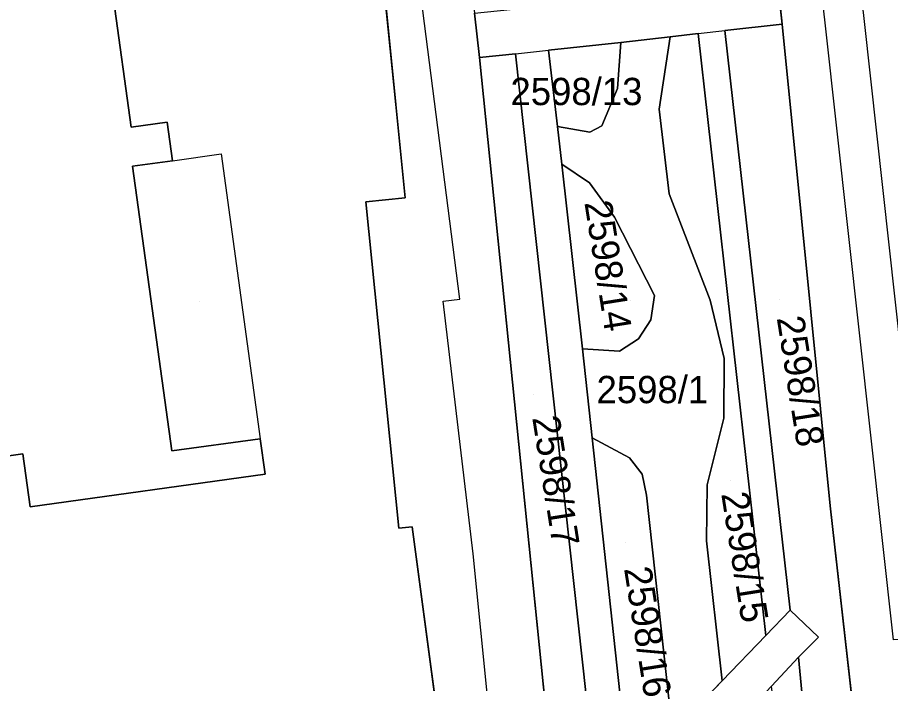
# Model space of a CAD drawing. Extents: x -263423 to -261326, y -1240067 to -1237864.
# Drawn here: x -263224.1 to -263160.1, y -1239953.5 to -1239904.7 of the extents above; entities that cross this region are included whole.
import ezdxf

# ---------------------------------------------------------------- set-up
doc = ezdxf.new("R2010")
doc.units = 0
for name, color, linetype in [('body_kn', 7, 'Continuous'), ('kladpar_druhypozemkov', 7, 'Continuous'), ('kladpar_hranice', 7, 'Continuous'), ('kladpar_parcelnecisla', 7, 'Continuous'), ('kladpar_plochy', 7, 'Continuous'), ('tarchy_linie', 7, 'Continuous'), ('zappar_hrandruhpozemk', 7, 'Continuous')]:
    doc.layers.add(name, color=color, linetype=linetype)

msp = doc.modelspace()

# ---------------------------------------------------------------- linework, layer by layer
at = {"layer": 'body_kn'}
for p, q in [((-263168.05, -1239905.15), (-263168.05, -1239905.15)), ((-263164.87, -1239905.28), (-263164.87, -1239905.28)), ((-263162.04, -1239904.96), (-263162.04, -1239904.96)), ((-263174.2, -1239905.83), (-263174.2, -1239905.83)), ((-263174.2, -1239905.83), (-263174.2, -1239905.83)), ((-263172.25, -1239905.62), (-263172.25, -1239905.62)), ((-263172.25, -1239905.62), (-263172.25, -1239905.62)), ((-263179.86, -1239906.49), (-263179.86, -1239906.49)), ((-263179.86, -1239906.49), (-263179.86, -1239906.49)), ((-263176.25, -1239906.08), (-263176.25, -1239906.08)), ((-263176.25, -1239906.08), (-263176.25, -1239906.08)), ((-263185.17, -1239907.05), (-263185.17, -1239907.05)), ((-263185.17, -1239907.05), (-263185.17, -1239907.05)), ((-263190.22, -1239907.6), (-263190.22, -1239907.6)), ((-263190.22, -1239907.6), (-263190.22, -1239907.6)), ((-263187.59, -1239907.31), (-263187.59, -1239907.31)), ((-263187.59, -1239907.31), (-263187.59, -1239907.31)), ((-263180.1, -1239909.85), (-263180.1, -1239909.85)), ((-263196.35, -1239911.03), (-263196.35, -1239911.03)), ((-263177.05, -1239911.38), (-263177.05, -1239911.38)), ((-263213.1, -1239912.33), (-263213.1, -1239912.33)), ((-263215.73, -1239912.69), (-263215.73, -1239912.69)), ((-263184.51, -1239912.65), (-263184.51, -1239912.65)), ((-263181.26, -1239912.6), (-263181.26, -1239912.6)), ((-263182.13, -1239913.06), (-263182.13, -1239913.06)), ((-263209.14, -1239914.66), (-263209.14, -1239914.66)), ((-263212.71, -1239915.15), (-263212.71, -1239915.15)), ((-263212.71, -1239915.15), (-263212.71, -1239915.15)), ((-263184.18, -1239915.4), (-263184.18, -1239915.4)), ((-263184.18, -1239915.4), (-263184.18, -1239915.4)), ((-263215.62, -1239915.55), (-263215.62, -1239915.55)), ((-263182.17, -1239916.78), (-263182.17, -1239916.78)), ((-263195.65, -1239917.88), (-263195.65, -1239917.88)), ((-263176.32, -1239917.58), (-263176.32, -1239917.58)), ((-263198.53, -1239918.17), (-263198.53, -1239918.17)), ((-263180.32, -1239919.28), (-263180.32, -1239919.28)), ((-263177.39, -1239925.04), (-263177.39, -1239925.04)), ((-263192.87, -1239925.44), (-263192.87, -1239925.44)), ((-263191.66, -1239925.31), (-263191.66, -1239925.31)), ((-263173.31, -1239925.38), (-263173.31, -1239925.38)), ((-263177.66, -1239926.81), (-263177.66, -1239926.81)), ((-263178.56, -1239928.2), (-263178.56, -1239928.2)), ((-263182.68, -1239928.94), (-263182.68, -1239928.94)), ((-263179.95, -1239929.11), (-263179.95, -1239929.11)), ((-263172.29, -1239929.64), (-263172.29, -1239929.64)), ((-263172.32, -1239934.02), (-263172.32, -1239934.02)), ((-263206.27, -1239935.53), (-263206.27, -1239935.53)), ((-263181.97, -1239935.45), (-263181.97, -1239935.45)), ((-263181.97, -1239935.45), (-263181.97, -1239935.45)), ((-263212.75, -1239936.42), (-263212.75, -1239936.42)), ((-263223.67, -1239936.64), (-263223.67, -1239936.64)), ((-263179.23, -1239936.92), (-263179.23, -1239936.92)), ((-263205.91, -1239938.12), (-263205.91, -1239938.12)), ((-263178.31, -1239938.12), (-263178.31, -1239938.12)), ((-263173.54, -1239938.91), (-263173.54, -1239938.91)), ((-263177.98, -1239939.66), (-263177.98, -1239939.66)), ((-263164.52, -1239940.44), (-263164.52, -1239940.44)), ((-263223.13, -1239940.51), (-263223.13, -1239940.51)), ((-263196.12, -1239942.09), (-263196.12, -1239942.09)), ((-263195.14, -1239941.99), (-263195.14, -1239941.99)), ((-263173.59, -1239943), (-263173.59, -1239943)), ((-263190.68, -1239943.95), (-263190.68, -1239943.95)), ((-263167.47, -1239948.09), (-263167.47, -1239948.09)), ((-263169.24, -1239949.95), (-263169.24, -1239949.95)), ((-263169.24, -1239949.95), (-263169.24, -1239949.95)), ((-263165.39, -1239950.06), (-263165.39, -1239950.06)), ((-263166.86, -1239951.52), (-263166.86, -1239951.52)), ((-263172.45, -1239953.27), (-263172.45, -1239953.27))]:
    msp.add_line(p, q, dxfattribs=at)
at = {"layer": 'kladpar_druhypozemkov'}
for p, q in [((-263182.81, -1239908.62), (-263182.81, -1239908.62)), ((-263210.71, -1239925.47), (-263210.71, -1239925.47)), ((-263179.12, -1239925.4), (-263179.12, -1239925.4)), ((-263168.22, -1239925.29), (-263168.22, -1239925.29)), ((-263177.05, -1239931.08), (-263177.05, -1239931.08)), ((-263186.24, -1239932.27), (-263186.24, -1239932.27)), ((-263171.86, -1239938.61), (-263171.86, -1239938.61)), ((-263179.51, -1239943.11), (-263179.51, -1239943.11))]:
    msp.add_line(p, q, dxfattribs=at)
at = {"layer": 'kladpar_hranice'}
for points in [[(-263193.38, -1239955.18), (-263195.14, -1239941.99), (-263196.12, -1239942.09), (-263198.53, -1239918.17), (-263195.65, -1239917.88), (-263196.35, -1239911.03), (-263197.17, -1239902.86), (-263197.96, -1239896), (-263200.87, -1239896.38), (-263203.98, -1239872.45), (-263202.98, -1239872.32), (-263204.71, -1239859.15), (-263204.77, -1239856.81), (-263205.86, -1239847.27), (-263207.6, -1239832.39), (-263207.79, -1239830.68)], [(-263161.9, -1239963.77), (-263164.52, -1239940.44), (-263168.05, -1239905.15), (-263168.4, -1239901.9), (-263174.54, -1239845.62), (-263175.4, -1239842.65), (-263176.71, -1239841.42), (-263179.47, -1239841.16), (-263194.58, -1239842.51), (-263196.99, -1239843.82), (-263197.78, -1239846.18), (-263196.99, -1239852.35), (-263190.58, -1239904.35), (-263190.22, -1239907.6), (-263184.32, -1239965.74)], [(-263178.81, -1239846.85), (-263172.6, -1239902.36), (-263168.4, -1239901.9), (-263168.05, -1239905.15), (-263172.25, -1239905.62), (-263167.47, -1239948.09), (-263165.39, -1239950.06), (-263166.86, -1239951.52), (-263165.62, -1239964.33), (-263167.57, -1239964.63), (-263168.82, -1239953.66), (-263172.04, -1239957.08), (-263175.64, -1239960.83), (-263178.87, -1239964.17), (-263178.63, -1239966.32), (-263181.06, -1239966.48), (-263184.15, -1239967.16), (-263184.32, -1239965.74), (-263181.47, -1239962.77), (-263187.59, -1239907.31), (-263190.22, -1239907.6), (-263190.58, -1239904.35), (-263187.96, -1239904.06)], [(-263244.26, -1239865.92), (-263215.75, -1239862.51), (-263215.99, -1239860.48), (-263204.71, -1239859.15), (-263202.98, -1239872.32), (-263203.98, -1239872.45), (-263200.87, -1239896.38), (-263197.96, -1239896), (-263197.17, -1239902.86), (-263196.35, -1239911.03), (-263195.65, -1239917.88), (-263198.53, -1239918.17), (-263196.12, -1239942.09), (-263195.14, -1239941.99), (-263193.38, -1239955.18)], [(-263239.81, -1239883.6), (-263231.06, -1239882.45), (-263231.59, -1239878.45), (-263214.34, -1239876.16), (-263213.98, -1239878.84), (-263220.46, -1239879.71), (-263217.65, -1239900.62), (-263214.77, -1239900.23), (-263214.4, -1239902.93), (-263217.02, -1239903.29), (-263215.73, -1239912.69), (-263213.1, -1239912.33), (-263212.71, -1239915.15), (-263215.62, -1239915.55), (-263212.75, -1239936.42), (-263206.27, -1239935.53), (-263205.91, -1239938.12), (-263223.13, -1239940.51), (-263223.67, -1239936.64), (-263229.66, -1239937.48)], [(-263229.66, -1239937.48), (-263223.67, -1239936.64), (-263223.13, -1239940.51), (-263205.91, -1239938.12), (-263206.27, -1239935.53), (-263212.75, -1239936.42), (-263215.62, -1239915.55), (-263212.71, -1239915.15), (-263213.1, -1239912.33), (-263215.73, -1239912.69), (-263217.02, -1239903.29), (-263214.4, -1239902.93), (-263214.77, -1239900.23), (-263217.65, -1239900.62), (-263220.46, -1239879.71), (-263213.98, -1239878.84), (-263214.34, -1239876.16), (-263231.59, -1239878.45), (-263231.06, -1239882.45)], [(-263172.25, -1239905.62), (-263168.05, -1239905.15), (-263164.52, -1239940.44), (-263161.9, -1239963.77), (-263165.62, -1239964.33), (-263166.86, -1239951.52), (-263165.39, -1239950.06), (-263167.47, -1239948.09), (-263172.25, -1239905.62)], [(-263185.17, -1239907.05), (-263184.51, -1239912.65), (-263184.18, -1239915.4), (-263182.68, -1239928.94), (-263181.97, -1239935.45), (-263179.26, -1239960.44), (-263176.07, -1239957.04), (-263172.45, -1239953.27), (-263169.24, -1239949.95), (-263174.2, -1239905.83), (-263176.25, -1239906.08), (-263179.86, -1239906.49), (-263185.17, -1239907.05)], [(-263176.25, -1239906.08), (-263174.2, -1239905.83), (-263169.24, -1239949.95), (-263172.45, -1239953.27), (-263173.59, -1239943), (-263173.54, -1239938.91), (-263172.32, -1239934.02), (-263172.29, -1239929.64), (-263173.31, -1239925.38), (-263176.32, -1239917.58), (-263177.05, -1239911.38), (-263176.25, -1239906.08)], [(-263185.17, -1239907.05), (-263179.86, -1239906.49), (-263180.1, -1239909.85), (-263181.26, -1239912.6), (-263182.13, -1239913.06), (-263184.51, -1239912.65), (-263185.17, -1239907.05)], [(-263179.86, -1239906.49), (-263176.25, -1239906.08), (-263177.05, -1239911.38), (-263176.32, -1239917.58), (-263173.31, -1239925.38), (-263172.29, -1239929.64), (-263172.32, -1239934.02), (-263173.54, -1239938.91), (-263173.59, -1239943), (-263172.45, -1239953.27), (-263176.07, -1239957.04), (-263177.98, -1239939.66), (-263178.31, -1239938.12), (-263179.23, -1239936.92), (-263181.97, -1239935.45), (-263182.68, -1239928.94), (-263179.95, -1239929.11), (-263178.56, -1239928.2), (-263177.66, -1239926.81), (-263177.39, -1239925.04), (-263180.32, -1239919.28), (-263182.17, -1239916.78), (-263184.18, -1239915.4), (-263184.51, -1239912.65), (-263182.13, -1239913.06), (-263181.26, -1239912.6), (-263180.1, -1239909.85), (-263179.86, -1239906.49)], [(-263190.22, -1239907.6), (-263187.59, -1239907.31), (-263181.47, -1239962.77), (-263184.32, -1239965.74), (-263190.22, -1239907.6)], [(-263184.18, -1239915.4), (-263182.17, -1239916.78), (-263180.32, -1239919.28), (-263177.39, -1239925.04), (-263177.66, -1239926.81), (-263178.56, -1239928.2), (-263179.95, -1239929.11), (-263182.68, -1239928.94), (-263184.18, -1239915.4)], [(-263181.97, -1239935.45), (-263179.23, -1239936.92), (-263178.31, -1239938.12), (-263177.98, -1239939.66), (-263176.07, -1239957.04), (-263179.26, -1239960.44), (-263181.97, -1239935.45)]]:
    msp.add_lwpolyline(points, dxfattribs=at)
at = {"layer": 'kladpar_plochy'}
for p, q in [((-263168.4, -1239901.9), (-263168.05, -1239905.15)), ((-263168.05, -1239905.15), (-263168.4, -1239901.9)), ((-263215.73, -1239912.69), (-263217.02, -1239903.29)), ((-263197.17, -1239902.86), (-263196.35, -1239911.03)), ((-263196.35, -1239911.03), (-263197.17, -1239902.86)), ((-263190.22, -1239907.6), (-263190.58, -1239904.35)), ((-263190.58, -1239904.35), (-263190.22, -1239907.6)), ((-263168.05, -1239905.15), (-263172.25, -1239905.62)), ((-263164.52, -1239940.44), (-263168.05, -1239905.15)), ((-263174.2, -1239905.83), (-263176.25, -1239906.08)), ((-263169.24, -1239949.95), (-263174.2, -1239905.83)), ((-263172.25, -1239905.62), (-263167.47, -1239948.09)), ((-263179.86, -1239906.49), (-263185.17, -1239907.05)), ((-263176.25, -1239906.08), (-263179.86, -1239906.49)), ((-263185.17, -1239907.05), (-263184.51, -1239912.65)), ((-263187.59, -1239907.31), (-263190.22, -1239907.6)), ((-263190.22, -1239907.6), (-263184.32, -1239965.74)), ((-263181.47, -1239962.77), (-263187.59, -1239907.31)), ((-263196.35, -1239911.03), (-263195.65, -1239917.88)), ((-263195.65, -1239917.88), (-263196.35, -1239911.03)), ((-263213.1, -1239912.33), (-263215.73, -1239912.69)), ((-263212.71, -1239915.15), (-263213.1, -1239912.33)), ((-263184.51, -1239912.65), (-263184.18, -1239915.4)), ((-263215.62, -1239915.55), (-263212.71, -1239915.15)), ((-263184.18, -1239915.4), (-263182.68, -1239928.94)), ((-263212.75, -1239936.42), (-263215.62, -1239915.55)), ((-263195.65, -1239917.88), (-263198.53, -1239918.17)), ((-263198.53, -1239918.17), (-263195.65, -1239917.88)), ((-263198.53, -1239918.17), (-263196.12, -1239942.09)), ((-263196.12, -1239942.09), (-263198.53, -1239918.17)), ((-263182.68, -1239928.94), (-263181.97, -1239935.45)), ((-263206.27, -1239935.53), (-263212.75, -1239936.42)), ((-263205.91, -1239938.12), (-263206.27, -1239935.53)), ((-263181.97, -1239935.45), (-263179.26, -1239960.44)), ((-263229.66, -1239937.48), (-263223.67, -1239936.64)), ((-263223.67, -1239936.64), (-263223.13, -1239940.51)), ((-263223.13, -1239940.51), (-263205.91, -1239938.12)), ((-263161.9, -1239963.77), (-263164.52, -1239940.44)), ((-263196.12, -1239942.09), (-263195.14, -1239941.99)), ((-263195.14, -1239941.99), (-263196.12, -1239942.09)), ((-263195.14, -1239941.99), (-263193.38, -1239955.18)), ((-263193.38, -1239955.18), (-263195.14, -1239941.99)), ((-263167.47, -1239948.09), (-263165.39, -1239950.06)), ((-263172.45, -1239953.27), (-263169.24, -1239949.95)), ((-263165.39, -1239950.06), (-263166.86, -1239951.52)), ((-263166.86, -1239951.52), (-263165.62, -1239964.33)), ((-263176.07, -1239957.04), (-263172.45, -1239953.27))]:
    msp.add_line(p, q, dxfattribs=at)
msp.add_lwpolyline([(-263231.59, -1239878.45), (-263214.34, -1239876.16), (-263213.98, -1239878.84), (-263220.46, -1239879.71), (-263217.65, -1239900.62), (-263214.77, -1239900.23), (-263214.4, -1239902.93), (-263217.02, -1239903.29), (-263215.73, -1239912.69), (-263213.1, -1239912.33), (-263212.71, -1239915.15), (-263215.62, -1239915.55), (-263212.75, -1239936.42), (-263206.27, -1239935.53), (-263205.91, -1239938.12), (-263223.13, -1239940.51), (-263223.67, -1239936.64), (-263229.66, -1239937.48)], dxfattribs=at)
for points in [[(-263172.25, -1239905.62), (-263168.05, -1239905.15), (-263164.52, -1239940.44), (-263161.9, -1239963.77), (-263165.62, -1239964.33), (-263166.86, -1239951.52), (-263165.39, -1239950.06), (-263167.47, -1239948.09)], [(-263176.25, -1239906.08), (-263174.2, -1239905.83), (-263169.24, -1239949.95), (-263172.45, -1239953.27), (-263173.59, -1239943), (-263173.54, -1239938.91), (-263172.32, -1239934.02), (-263172.29, -1239929.64), (-263173.31, -1239925.38), (-263176.32, -1239917.58), (-263177.05, -1239911.38)], [(-263185.17, -1239907.05), (-263179.86, -1239906.49), (-263180.1, -1239909.85), (-263181.26, -1239912.6), (-263182.13, -1239913.06), (-263184.51, -1239912.65)], [(-263179.86, -1239906.49), (-263176.25, -1239906.08), (-263177.05, -1239911.38), (-263176.32, -1239917.58), (-263173.31, -1239925.38), (-263172.29, -1239929.64), (-263172.32, -1239934.02), (-263173.54, -1239938.91), (-263173.59, -1239943), (-263172.45, -1239953.27), (-263176.07, -1239957.04), (-263177.98, -1239939.66), (-263178.31, -1239938.12), (-263179.23, -1239936.92), (-263181.97, -1239935.45), (-263182.68, -1239928.94), (-263179.95, -1239929.11), (-263178.56, -1239928.2), (-263177.66, -1239926.81), (-263177.39, -1239925.04), (-263180.32, -1239919.28), (-263182.17, -1239916.78), (-263184.18, -1239915.4), (-263184.51, -1239912.65), (-263182.13, -1239913.06), (-263181.26, -1239912.6), (-263180.1, -1239909.85)], [(-263190.22, -1239907.6), (-263187.59, -1239907.31), (-263181.47, -1239962.77), (-263184.32, -1239965.74)], [(-263184.18, -1239915.4), (-263182.17, -1239916.78), (-263180.32, -1239919.28), (-263177.39, -1239925.04), (-263177.66, -1239926.81), (-263178.56, -1239928.2), (-263179.95, -1239929.11), (-263182.68, -1239928.94)], [(-263181.97, -1239935.45), (-263179.23, -1239936.92), (-263178.31, -1239938.12), (-263177.98, -1239939.66), (-263176.07, -1239957.04), (-263179.26, -1239960.44)]]:
    msp.add_lwpolyline(points, close=True, dxfattribs=at)
at = {"layer": 'tarchy_linie'}
for points in [[(-263185.2, -1239701.74), (-263177.2, -1239769.3), (-263169.7, -1239837.34), (-263162.04, -1239904.96), (-263157.06, -1239950.07)], [(-263160.13, -1239831.12), (-263160.13, -1239832.68), (-263162.85, -1239832.94), (-263162.7, -1239835.06), (-263160.13, -1239834.82), (-263160.12, -1239836.48), (-263160.12, -1239838.14), (-263162.45, -1239838.36), (-263159.29, -1239881.2), (-263150.78, -1239949.66), (-263152.42, -1239949.77), (-263157.06, -1239950.07), (-263159.9, -1239950.26), (-263164.87, -1239905.28), (-263172.53, -1239837.66), (-263180.03, -1239769.62)]]:
    msp.add_lwpolyline(points, dxfattribs=at)
at = {"layer": 'zappar_hrandruhpozemk'}
for p, q in [((-263191.66, -1239925.31), (-263195.51, -1239895.22)), ((-263174.2, -1239905.83), (-263172.25, -1239905.62)), ((-263187.59, -1239907.31), (-263185.17, -1239907.05)), ((-263212.71, -1239915.15), (-263209.14, -1239914.66)), ((-263209.14, -1239914.66), (-263206.27, -1239935.53)), ((-263169.24, -1239949.95), (-263167.47, -1239948.09)), ((-263168.82, -1239953.66), (-263166.86, -1239951.52))]:
    msp.add_line(p, q, dxfattribs=at)
msp.add_lwpolyline([(-263189.01, -1239960.5), (-263190.68, -1239943.95), (-263192.87, -1239925.44), (-263191.66, -1239925.31)], dxfattribs=at)

# ---------------------------------------------------------------- texts
at = {"layer": 'kladpar_parcelnecisla'}
for s, p in [('2598/13', (-263187.947, -1239911.08)), ('2598/1', (-263181.644, -1239932.92))]:
    msp.add_text(s, height=2, dxfattribs=at).set_placement(p)
for s, p in [('2598/14', (-263182.536, -1239918.219)), ('2598/18', (-263168.45, -1239926.675)), ('2598/17', (-263186.359, -1239933.985)), ('2598/15', (-263172.515, -1239939.564)), ('2598/16', (-263179.636, -1239945.039))]:
    msp.add_text(s, height=2, rotation=279, dxfattribs=at).set_placement(p)

doc.saveas('drawing.dxf')
